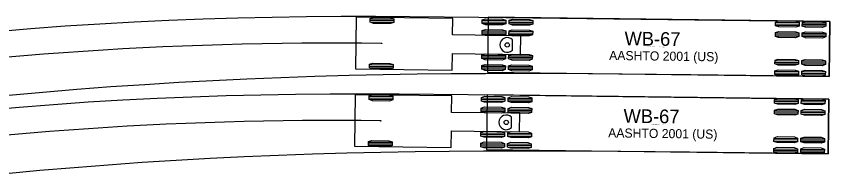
# Model space of a CAD drawing. Extents: x 1639988 to 1641860, y 841974 to 844187.
# Drawn here: x 1641179.4 to 1641305.6, y 842694.8 to 842719.2 of the extents above; entities that cross this region are included whole.
import ezdxf

# ---------------------------------------------------------------- set-up
doc = ezdxf.new("R2010")
doc.units = 0
doc.layers.add('Scratch_Level_1', color=7, linetype='Continuous')

msp = doc.modelspace()

# ---------------------------------------------------------------- linework, layer by layer
at = {"layer": 'Scratch_Level_1'}
for p, q in [((1641232.14, 842719.06), (1641232.04, 842711.06)), ((1641247.14, 842718.87), (1641232.14, 842719.06)), ((1641234.31, 842718.8), (1641237.97, 842718.76)), ((1641247.11, 842716.31), (1641247.14, 842718.87)), ((1641252.65, 842719.05), (1641252.54, 842710.55)), ((1641305.64, 842718.39), (1641252.65, 842719.05)), ((1641234.3, 842718.58), (1641237.97, 842718.53)), ((1641234.3, 842718.35), (1641237.97, 842718.3)), ((1641251.72, 842718.59), (1641255.39, 842718.54)), ((1641251.72, 842718.36), (1641255.39, 842718.31)), ((1641251.72, 842718.13), (1641255.38, 842718.08)), ((1641255.88, 842718.08), (1641259.55, 842718.03)), ((1641255.89, 842718.53), (1641259.56, 842718.49)), ((1641255.89, 842718.31), (1641259.55, 842718.26)), ((1641297.22, 842718.27), (1641300.89, 842718.22)), ((1641297.22, 842718.04), (1641300.89, 842717.99)), ((1641297.22, 842717.81), (1641300.88, 842717.76)), ((1641301.38, 842717.76), (1641305.05, 842717.71)), ((1641301.39, 842718.21), (1641305.06, 842718.17)), ((1641301.39, 842717.98), (1641305.05, 842717.94)), ((1641305.53, 842709.89), (1641305.64, 842718.39)), ((1641257.69, 842716.17), (1641247.11, 842716.31)), ((1641251.7, 842716.94), (1641255.37, 842716.89)), ((1641251.7, 842716.71), (1641255.37, 842716.66)), ((1641251.7, 842716.48), (1641255.36, 842716.43)), ((1641255.86, 842716.43), (1641259.53, 842716.38)), ((1641255.87, 842716.88), (1641259.54, 842716.84)), ((1641255.87, 842716.66), (1641259.53, 842716.61)), ((1641257.66, 842713.31), (1641257.69, 842716.17)), ((1641297.2, 842716.62), (1641300.87, 842716.57)), ((1641297.2, 842716.39), (1641300.87, 842716.34)), ((1641297.2, 842716.16), (1641300.86, 842716.11)), ((1641301.37, 842716.56), (1641305.03, 842716.52)), ((1641301.37, 842716.33), (1641305.03, 842716.29)), ((1641256.39, 842713.95), (1641256.41, 842715.56)), ((1641301.36, 842716.11), (1641305.03, 842716.06)), ((1641247.04, 842710.87), (1641247.07, 842713.44)), ((1641247.07, 842713.44), (1641257.66, 842713.31)), ((1641251.65, 842713.15), (1641255.32, 842713.11)), ((1641251.65, 842712.92), (1641255.32, 842712.88)), ((1641251.65, 842712.7), (1641255.32, 842712.65)), ((1641255.82, 842713.1), (1641259.49, 842713.06)), ((1641255.82, 842712.87), (1641259.48, 842712.83)), ((1641255.82, 842712.64), (1641259.48, 842712.6)), ((1641297.15, 842712.33), (1641300.81, 842712.29)), ((1641234.21, 842711.26), (1641237.88, 842711.22)), ((1641234.22, 842711.72), (1641237.89, 842711.68)), ((1641234.22, 842711.49), (1641237.88, 842711.45)), ((1641251.63, 842711.5), (1641255.3, 842711.46)), ((1641251.63, 842711.27), (1641255.3, 842711.23)), ((1641255.8, 842711.45), (1641259.47, 842711.41)), ((1641255.8, 842711.22), (1641259.46, 842711.18)), ((1641297.14, 842711.87), (1641300.81, 842711.83)), ((1641297.15, 842712.1), (1641300.81, 842712.06)), ((1641301.31, 842712.28), (1641304.98, 842712.23)), ((1641301.31, 842712.05), (1641304.98, 842712.01)), ((1641301.31, 842711.82), (1641304.98, 842711.78)), ((1641232.04, 842711.06), (1641247.04, 842710.87)), ((1641232.04, 842711.06), (1641232.04, 842711.06)), ((1641251.63, 842711.05), (1641255.29, 842711)), ((1641252.54, 842710.55), (1641305.53, 842709.89)), ((1641252.54, 842710.55), (1641252.54, 842710.55)), ((1641255.79, 842710.99), (1641259.46, 842710.95)), ((1641297.12, 842710.45), (1641300.79, 842710.41)), ((1641297.12, 842710.22), (1641300.79, 842710.18)), ((1641297.13, 842710.68), (1641300.79, 842710.64)), ((1641301.29, 842710.63), (1641304.96, 842710.58)), ((1641301.29, 842710.4), (1641304.96, 842710.36)), ((1641301.29, 842710.17), (1641304.95, 842710.13)), ((1641231.99, 842707.06), (1641231.89, 842699.06)), ((1641246.99, 842706.87), (1641231.99, 842707.06)), ((1641234.15, 842706.58), (1641237.82, 842706.53)), ((1641234.15, 842706.35), (1641237.82, 842706.3)), ((1641234.16, 842706.81), (1641237.82, 842706.76)), ((1641246.96, 842704.31), (1641246.99, 842706.87)), ((1641251.57, 842706.59), (1641255.24, 842706.54)), ((1641251.57, 842706.36), (1641255.24, 842706.31)), ((1641251.57, 842706.13), (1641255.23, 842706.08)), ((1641252.5, 842707.06), (1641252.39, 842698.56)), ((1641305.49, 842706.39), (1641252.5, 842707.06)), ((1641255.73, 842706.08), (1641259.4, 842706.03)), ((1641255.74, 842706.54), (1641259.41, 842706.49)), ((1641255.74, 842706.31), (1641259.4, 842706.26)), ((1641297.07, 842706.27), (1641300.74, 842706.22)), ((1641297.07, 842706.04), (1641300.74, 842705.99)), ((1641301.24, 842706.21), (1641304.9, 842706.17)), ((1641305.38, 842697.89), (1641305.49, 842706.39)), ((1641251.55, 842704.94), (1641255.22, 842704.89)), ((1641255.72, 842704.89), (1641259.38, 842704.84)), ((1641297.07, 842705.81), (1641300.73, 842705.76)), ((1641301.23, 842705.76), (1641304.9, 842705.71)), ((1641301.24, 842705.99), (1641304.9, 842705.94)), ((1641257.54, 842704.17), (1641246.96, 842704.31)), ((1641251.55, 842704.71), (1641255.22, 842704.66)), ((1641251.55, 842704.48), (1641255.21, 842704.43)), ((1641255.71, 842704.43), (1641259.38, 842704.38)), ((1641255.72, 842704.66), (1641259.38, 842704.61)), ((1641256.24, 842701.95), (1641256.26, 842703.57)), ((1641257.51, 842701.31), (1641257.54, 842704.17)), ((1641297.05, 842704.62), (1641300.72, 842704.57)), ((1641297.05, 842704.39), (1641300.71, 842704.34)), ((1641297.05, 842704.16), (1641300.71, 842704.11)), ((1641301.21, 842704.34), (1641304.88, 842704.29)), ((1641301.21, 842704.11), (1641304.88, 842704.06)), ((1641301.22, 842704.56), (1641304.88, 842704.52)), ((1641246.89, 842698.87), (1641246.92, 842701.44)), ((1641246.92, 842701.44), (1641257.51, 842701.31)), ((1641251.5, 842701.15), (1641255.17, 842701.11)), ((1641255.67, 842701.1), (1641259.34, 842701.06)), ((1641234.07, 842699.72), (1641237.73, 842699.68)), ((1641251.5, 842700.93), (1641255.17, 842700.88)), ((1641251.5, 842700.7), (1641255.17, 842700.65)), ((1641255.67, 842700.87), (1641259.33, 842700.83)), ((1641255.67, 842700.64), (1641259.33, 842700.6)), ((1641296.99, 842700.1), (1641300.66, 842700.06)), ((1641296.99, 842699.88), (1641300.66, 842699.83)), ((1641297, 842700.33), (1641300.66, 842700.29)), ((1641301.16, 842700.28), (1641304.83, 842700.24)), ((1641301.16, 842700.05), (1641304.83, 842700.01)), ((1641301.16, 842699.82), (1641304.82, 842699.78)), ((1641231.89, 842699.06), (1641246.89, 842698.87)), ((1641231.89, 842699.06), (1641231.89, 842699.06)), ((1641234.06, 842699.26), (1641237.73, 842699.22)), ((1641234.07, 842699.49), (1641237.73, 842699.45)), ((1641251.48, 842699.5), (1641255.15, 842699.46)), ((1641251.48, 842699.28), (1641255.15, 842699.23)), ((1641251.48, 842699.05), (1641255.14, 842699)), ((1641252.39, 842698.56), (1641305.38, 842697.89)), ((1641252.39, 842698.56), (1641252.39, 842698.56)), ((1641255.64, 842698.99), (1641259.31, 842698.95)), ((1641255.65, 842699.45), (1641259.32, 842699.41)), ((1641255.65, 842699.22), (1641259.31, 842699.18)), ((1641296.97, 842698.45), (1641300.64, 842698.41)), ((1641296.98, 842698.68), (1641300.64, 842698.64)), ((1641301.14, 842698.63), (1641304.81, 842698.59)), ((1641296.97, 842698.23), (1641300.64, 842698.18)), ((1641301.14, 842698.4), (1641304.81, 842698.36)), ((1641301.14, 842698.17), (1641304.8, 842698.13))]:
    msp.add_line(p, q, dxfattribs=at)
for points in [[(1641176.3, 842716.86), (1641181.65, 842717.31), (1641187, 842717.71), (1641192.35, 842718.06), (1641197.71, 842718.36), (1641203.07, 842718.61), (1641208.42, 842718.81), (1641213.76, 842718.96), (1641219.11, 842719.08), (1641224.46, 842719.16), (1641229.8, 842719.2), (1641235.15, 842719.21), (1641240.49, 842719.18), (1641251.17, 842719.07), (1641305.64, 842718.39), (1641305.53, 842709.89), (1641305.38, 842709.89), (1641305.38, 842709.89)], [(1641305.38, 842709.89), (1641284.07, 842710.15), (1641273.44, 842710.26), (1641262.82, 842710.32), (1641252.21, 842710.31), (1641246.91, 842710.28), (1641241.62, 842710.22), (1641236.33, 842710.13), (1641231.04, 842710.02), (1641225.75, 842709.87), (1641220.47, 842709.69), (1641215.19, 842709.48), (1641209.91, 842709.23), (1641204.63, 842708.94), (1641199.36, 842708.61), (1641194.08, 842708.25), (1641188.79, 842707.85), (1641183.52, 842707.41), (1641178.24, 842706.93)], [(1641174.5, 842704.65), (1641179.85, 842705.12), (1641185.19, 842705.55), (1641190.55, 842705.93), (1641195.91, 842706.25), (1641201.26, 842706.52), (1641206.63, 842706.75), (1641211.99, 842706.91), (1641217.36, 842707.04), (1641222.72, 842707.13), (1641228.09, 842707.19), (1641233.45, 842707.21), (1641238.81, 842707.19), (1641249.52, 842707.09), (1641305.49, 842706.39), (1641305.38, 842697.89), (1641305.26, 842697.89), (1641305.26, 842697.89)], [(1641305.26, 842697.89), (1641283.87, 842698.16), (1641273.2, 842698.26), (1641262.55, 842698.32), (1641257.23, 842698.33), (1641251.91, 842698.31), (1641246.6, 842698.27), (1641241.28, 842698.21), (1641235.98, 842698.12), (1641230.67, 842697.99), (1641225.37, 842697.84), (1641220.07, 842697.65), (1641214.77, 842697.43), (1641209.48, 842697.17), (1641204.19, 842696.88), (1641198.91, 842696.54), (1641193.63, 842696.16), (1641188.35, 842695.75), (1641183.07, 842695.3), (1641177.79, 842694.81)]]:
    msp.add_lwpolyline(points, dxfattribs=at)
for points in [[(1641234.3, 842718.29), (1641234.31, 842718.86), (1641234.82, 842719.03), (1641237.46, 842718.99), (1641237.97, 842718.82), (1641237.97, 842718.24), (1641237.45, 842718.08), (1641234.81, 842718.11)], [(1641251.72, 842718.07), (1641251.72, 842718.64), (1641252.24, 842718.81), (1641254.88, 842718.78), (1641255.39, 842718.6), (1641255.38, 842718.03), (1641254.87, 842717.86), (1641252.23, 842717.89)], [(1641255.88, 842718.02), (1641255.89, 842718.59), (1641256.41, 842718.76), (1641259.05, 842718.72), (1641259.56, 842718.55), (1641259.55, 842717.97), (1641259.03, 842717.81), (1641256.39, 842717.84)], [(1641297.22, 842717.75), (1641297.22, 842718.32), (1641297.74, 842718.49), (1641300.38, 842718.46), (1641300.89, 842718.28), (1641300.88, 842717.7), (1641300.37, 842717.54), (1641297.73, 842717.57)], [(1641301.38, 842717.7), (1641301.39, 842718.27), (1641301.91, 842718.44), (1641304.54, 842718.4), (1641305.06, 842718.22), (1641305.05, 842717.65), (1641304.53, 842717.49), (1641301.89, 842717.52)], [(1641251.7, 842716.42), (1641251.7, 842716.99), (1641252.22, 842717.16), (1641254.86, 842717.13), (1641255.37, 842716.95), (1641255.36, 842716.38), (1641254.85, 842716.21), (1641252.21, 842716.24)], [(1641255.86, 842716.37), (1641255.87, 842716.94), (1641256.38, 842717.11), (1641259.02, 842717.07), (1641259.54, 842716.9), (1641259.53, 842716.32), (1641259.01, 842716.16), (1641256.37, 842716.19)], [(1641297.2, 842716.1), (1641297.2, 842716.67), (1641297.72, 842716.84), (1641300.36, 842716.81), (1641300.87, 842716.63), (1641300.86, 842716.05), (1641300.35, 842715.89), (1641297.71, 842715.92)], [(1641301.36, 842716.05), (1641301.37, 842716.62), (1641301.88, 842716.79), (1641304.52, 842716.75), (1641305.04, 842716.57), (1641305.03, 842716), (1641304.51, 842715.84), (1641301.87, 842715.87)], [(1641251.65, 842712.64), (1641251.66, 842713.21), (1641252.17, 842713.38), (1641254.81, 842713.34), (1641255.32, 842713.16), (1641255.31, 842712.59), (1641254.8, 842712.43), (1641252.16, 842712.46)], [(1641255.81, 842712.59), (1641255.82, 842713.16), (1641256.34, 842713.32), (1641258.98, 842713.29), (1641259.49, 842713.11), (1641259.48, 842712.54), (1641258.97, 842712.37), (1641256.33, 842712.41)], [(1641297.14, 842711.82), (1641297.15, 842712.39), (1641297.66, 842712.56), (1641300.3, 842712.52), (1641300.82, 842712.34), (1641300.81, 842711.77), (1641300.29, 842711.61), (1641297.65, 842711.64)], [(1641301.31, 842711.77), (1641301.32, 842712.34), (1641301.83, 842712.5), (1641304.47, 842712.47), (1641304.98, 842712.29), (1641304.97, 842711.72), (1641304.46, 842711.55), (1641301.82, 842711.59)], [(1641234.21, 842711.21), (1641234.22, 842711.78), (1641234.74, 842711.94), (1641237.37, 842711.91), (1641237.89, 842711.73), (1641237.88, 842711.16), (1641237.36, 842711), (1641234.72, 842711.03)], [(1641251.63, 842710.99), (1641251.64, 842711.56), (1641252.15, 842711.73), (1641254.79, 842711.69), (1641255.3, 842711.51), (1641255.29, 842710.94), (1641254.78, 842710.78), (1641252.14, 842710.81)], [(1641255.79, 842710.94), (1641255.8, 842711.51), (1641256.32, 842711.67), (1641258.96, 842711.64), (1641259.47, 842711.46), (1641259.46, 842710.89), (1641258.95, 842710.72), (1641256.31, 842710.76)], [(1641297.12, 842710.17), (1641297.13, 842710.74), (1641297.64, 842710.91), (1641300.28, 842710.87), (1641300.79, 842710.69), (1641300.79, 842710.12), (1641300.27, 842709.96), (1641297.63, 842709.99)], [(1641301.29, 842710.12), (1641301.29, 842710.69), (1641301.81, 842710.85), (1641304.45, 842710.82), (1641304.96, 842710.64), (1641304.95, 842710.07), (1641304.44, 842709.9), (1641301.8, 842709.94)], [(1641234.15, 842706.29), (1641234.16, 842706.86), (1641234.67, 842707.03), (1641237.31, 842707), (1641237.82, 842706.82), (1641237.82, 842706.24), (1641237.3, 842706.08), (1641234.66, 842706.11)], [(1641251.57, 842706.07), (1641251.57, 842706.64), (1641252.09, 842706.81), (1641254.73, 842706.78), (1641255.24, 842706.6), (1641255.23, 842706.03), (1641254.72, 842705.86), (1641252.08, 842705.89)], [(1641255.73, 842706.02), (1641255.74, 842706.59), (1641256.26, 842706.76), (1641258.89, 842706.72), (1641259.41, 842706.55), (1641259.4, 842705.97), (1641258.88, 842705.81), (1641256.24, 842705.84)], [(1641297.07, 842705.75), (1641297.07, 842706.32), (1641297.59, 842706.49), (1641300.23, 842706.46), (1641300.74, 842706.28), (1641300.73, 842705.71), (1641300.22, 842705.54), (1641297.58, 842705.57)], [(1641301.23, 842705.7), (1641301.24, 842706.27), (1641301.75, 842706.44), (1641304.39, 842706.4), (1641304.91, 842706.23), (1641304.9, 842705.65), (1641304.38, 842705.49), (1641301.74, 842705.52)], [(1641251.55, 842704.42), (1641251.55, 842704.99), (1641252.07, 842705.16), (1641254.71, 842705.13), (1641255.22, 842704.95), (1641255.21, 842704.38), (1641254.7, 842704.21), (1641252.06, 842704.24)], [(1641255.71, 842704.37), (1641255.72, 842704.94), (1641256.23, 842705.11), (1641258.87, 842705.07), (1641259.39, 842704.9), (1641259.38, 842704.32), (1641258.86, 842704.16), (1641256.22, 842704.19)], [(1641297.05, 842704.1), (1641297.05, 842704.67), (1641297.57, 842704.84), (1641300.21, 842704.81), (1641300.72, 842704.63), (1641300.71, 842704.06), (1641300.2, 842703.89), (1641297.56, 842703.92)], [(1641301.21, 842704.05), (1641301.22, 842704.62), (1641301.73, 842704.79), (1641304.37, 842704.75), (1641304.88, 842704.58), (1641304.88, 842704), (1641304.36, 842703.84), (1641301.72, 842703.87)], [(1641251.5, 842700.64), (1641251.51, 842701.21), (1641252.02, 842701.38), (1641254.66, 842701.34), (1641255.17, 842701.17), (1641255.16, 842700.59), (1641254.65, 842700.43), (1641252.01, 842700.46)], [(1641255.66, 842700.59), (1641255.67, 842701.16), (1641256.19, 842701.33), (1641258.83, 842701.29), (1641259.34, 842701.11), (1641259.33, 842700.54), (1641258.82, 842700.38), (1641256.18, 842700.41)], [(1641234.06, 842699.21), (1641234.07, 842699.78), (1641234.58, 842699.95), (1641237.22, 842699.91), (1641237.74, 842699.73), (1641237.73, 842699.16), (1641237.21, 842699), (1641234.57, 842699.03)], [(1641251.48, 842698.99), (1641251.48, 842699.56), (1641252, 842699.73), (1641254.64, 842699.69), (1641255.15, 842699.52), (1641255.14, 842698.94), (1641254.63, 842698.78), (1641251.99, 842698.81)], [(1641296.99, 842699.82), (1641297, 842700.39), (1641297.51, 842700.56), (1641300.15, 842700.52), (1641300.66, 842700.34), (1641300.66, 842699.77), (1641300.14, 842699.61), (1641297.5, 842699.64)], [(1641301.16, 842699.77), (1641301.16, 842700.34), (1641301.68, 842700.5), (1641304.32, 842700.47), (1641304.83, 842700.29), (1641304.82, 842699.72), (1641304.31, 842699.55), (1641301.67, 842699.59)], [(1641255.64, 842698.94), (1641255.65, 842699.51), (1641256.17, 842699.68), (1641258.81, 842699.64), (1641259.32, 842699.46), (1641259.31, 842698.89), (1641258.79, 842698.73), (1641256.15, 842698.76)], [(1641296.97, 842698.17), (1641296.98, 842698.74), (1641297.49, 842698.91), (1641300.13, 842698.87), (1641300.64, 842698.69), (1641300.64, 842698.12), (1641300.12, 842697.96), (1641297.48, 842697.99)], [(1641301.14, 842698.12), (1641301.14, 842698.69), (1641301.66, 842698.85), (1641304.3, 842698.82), (1641304.81, 842698.64), (1641304.8, 842698.07), (1641304.29, 842697.9), (1641301.65, 842697.94)]]:
    msp.add_lwpolyline(points, close=True, dxfattribs=at)
for centre, radius in [((1641236.09, 842715.01), 0.0417), ((1641255.59, 842714.77), 0.34), ((1641235.94, 842703.01), 0.0417), ((1641255.44, 842702.77), 0.34)]:
    msp.add_circle(centre, radius, dxfattribs=at)
for centre, radius, start, end in [((1641228.74, 842129.06), 586, 89.28137, 98.94492), ((1641255.59, 842714.77), 1.14, 44.2814, 314.2814), ((1641255.44, 842702.77), 1.14, 44.2814, 314.2814), ((1641228.74, 842129.06), 574, 89.28137, 98.94492)]:
    msp.add_arc(centre, radius, start, end, dxfattribs=at)

# ---------------------------------------------------------------- texts
for s, height, p in [('WB-67', 2.125, (1641273.78, 842714.71)), ('AASHTO 2001 (US)', 1.4167, (1641271.4, 842712.44)), ('(c) 2019 Transoft Solutions, Inc. All rights reserved.', 0.085, (1641277.36, 842714.45)), ('WB-67', 2.125, (1641273.63, 842702.71)), ('(c) 2019 Transoft Solutions, Inc. All rights reserved.', 0.085, (1641277.21, 842702.45)), ('AASHTO 2001 (US)', 1.4167, (1641271.25, 842700.44))]:
    msp.add_text(s, height=height, rotation=359.2814, dxfattribs=at).set_placement(p)

doc.saveas('drawing.dxf')
